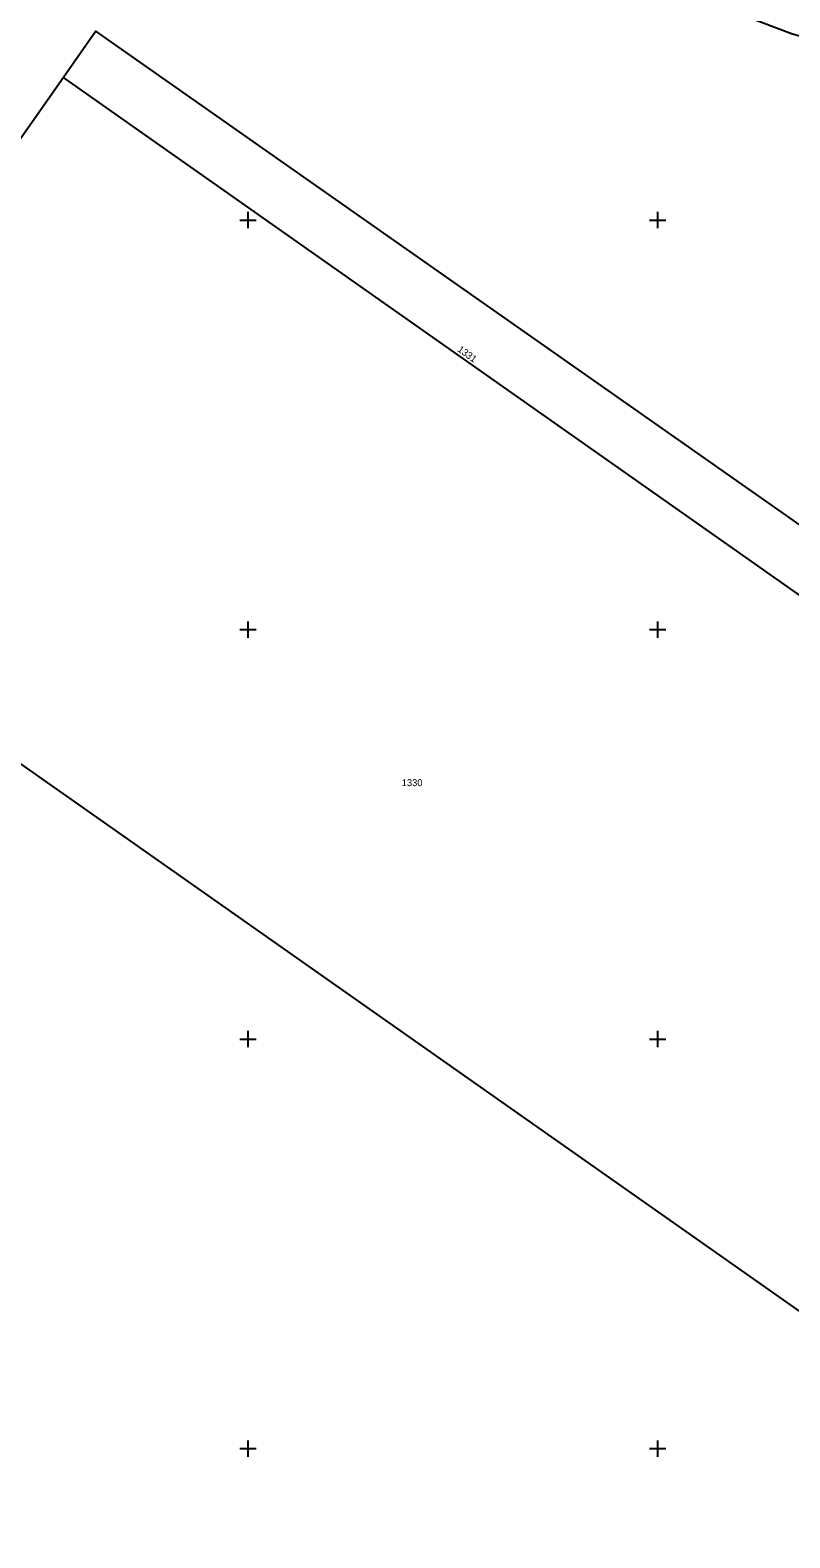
# Model space of a CAD drawing. Extents: x -711234 to -710007, y -1026313 to -1025448.
# Drawn here: x -710963.3 to -710916.9, y -1026055.5 to -1025963.4 of the extents above; entities that cross this region are included whole.
import ezdxf

# ---------------------------------------------------------------- set-up
doc = ezdxf.new("R2010")
doc.units = 0
for name, color, linetype in [('Ex_Major Contours', 7, 'Continuous'), ('Z_hektometricka_sit', 7, 'Continuous'), ('Z_katastr_cisla_pozemkova', 7, 'Continuous'), ('Z_katastr_hranice', 7, 'Continuous')]:
    doc.layers.add(name, color=color, linetype=linetype)

msp = doc.modelspace()

# ---------------------------------------------------------------- linework, layer by layer
at = {"layer": 'Ex_Major Contours'}
msp.add_lwpolyline([(-710926.145, -1025960.075), (-710916.837, -1025963.602), (-710916.269, -1025963.781), (-710915.691, -1025963.891), (-710915.105, -1025963.93), (-710914.51, -1025963.9), (-710911.236, -1025963.544), (-710911.075, -1025963.522), (-710910.915, -1025963.491), (-710910.757, -1025963.451), (-710910.601, -1025963.401), (-710909.982, -1025963.186), (-710909.837, -1025963.157), (-710909.709, -1025963.176), (-710909.6, -1025963.244), (-710909.508, -1025963.362), (-710908.812, -1025964.556), (-710908.677, -1025964.805), (-710908.557, -1025965.062), (-710908.453, -1025965.325), (-710908.365, -1025965.595), (-710906.758, -1025971.097)], dxfattribs=at)
at = {"layer": 'Z_hektometricka_sit'}
for p, q in [((-710950, -1025974.5), (-710950, -1025975.5)), ((-710925, -1025974.5), (-710925, -1025975.5)), ((-710950.5, -1025975), (-710949.5, -1025975)), ((-710925.5, -1025975), (-710924.5, -1025975)), ((-710950, -1025999.5), (-710950, -1026000.5)), ((-710925, -1025999.5), (-710925, -1026000.5)), ((-710950.5, -1026000), (-710949.5, -1026000)), ((-710925.5, -1026000), (-710924.5, -1026000)), ((-710950, -1026024.5), (-710950, -1026025.5)), ((-710925, -1026024.5), (-710925, -1026025.5)), ((-710950.5, -1026025), (-710949.5, -1026025)), ((-710925.5, -1026025), (-710924.5, -1026025)), ((-710950.5, -1026050), (-710949.5, -1026050)), ((-710950, -1026049.5), (-710950, -1026050.5)), ((-710925.5, -1026050), (-710924.5, -1026050)), ((-710925, -1026049.5), (-710925, -1026050.5))]:
    msp.add_line(p, q, dxfattribs=at)
at = {"layer": 'Z_katastr_hranice'}
for p, q in [((-710961.26, -1025966.3), (-710981.8, -1025995.57)), ((-710902.45, -1026007.68), (-710961.26, -1025966.3)), ((-710896.69, -1026055.45), (-710981.8, -1025995.57))]:
    msp.add_line(p, q, dxfattribs=at)
msp.add_lwpolyline([(-710903.02, -1026002.95), (-710959.27, -1025963.47), (-710961.26, -1025966.3)], dxfattribs=at)

# ---------------------------------------------------------------- texts
at = {"layer": 'Z_katastr_cisla_pozemkova'}
msp.add_text('1331', height=0.425, rotation=324, dxfattribs=at).set_placement((-710937.249, -1025982.977))
msp.add_text('1330', height=0.425, dxfattribs=at).set_placement((-710940.61, -1026009.559))

doc.saveas('drawing.dxf')
